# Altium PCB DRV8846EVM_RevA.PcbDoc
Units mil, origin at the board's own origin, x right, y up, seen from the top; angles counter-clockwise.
Board outline 2000 x 3000 mil, 2 copper layers (Top Layer, Bottom Layer), stack 62 mil thick; 51 components, 58 nets, 255 pads, 188 vias.
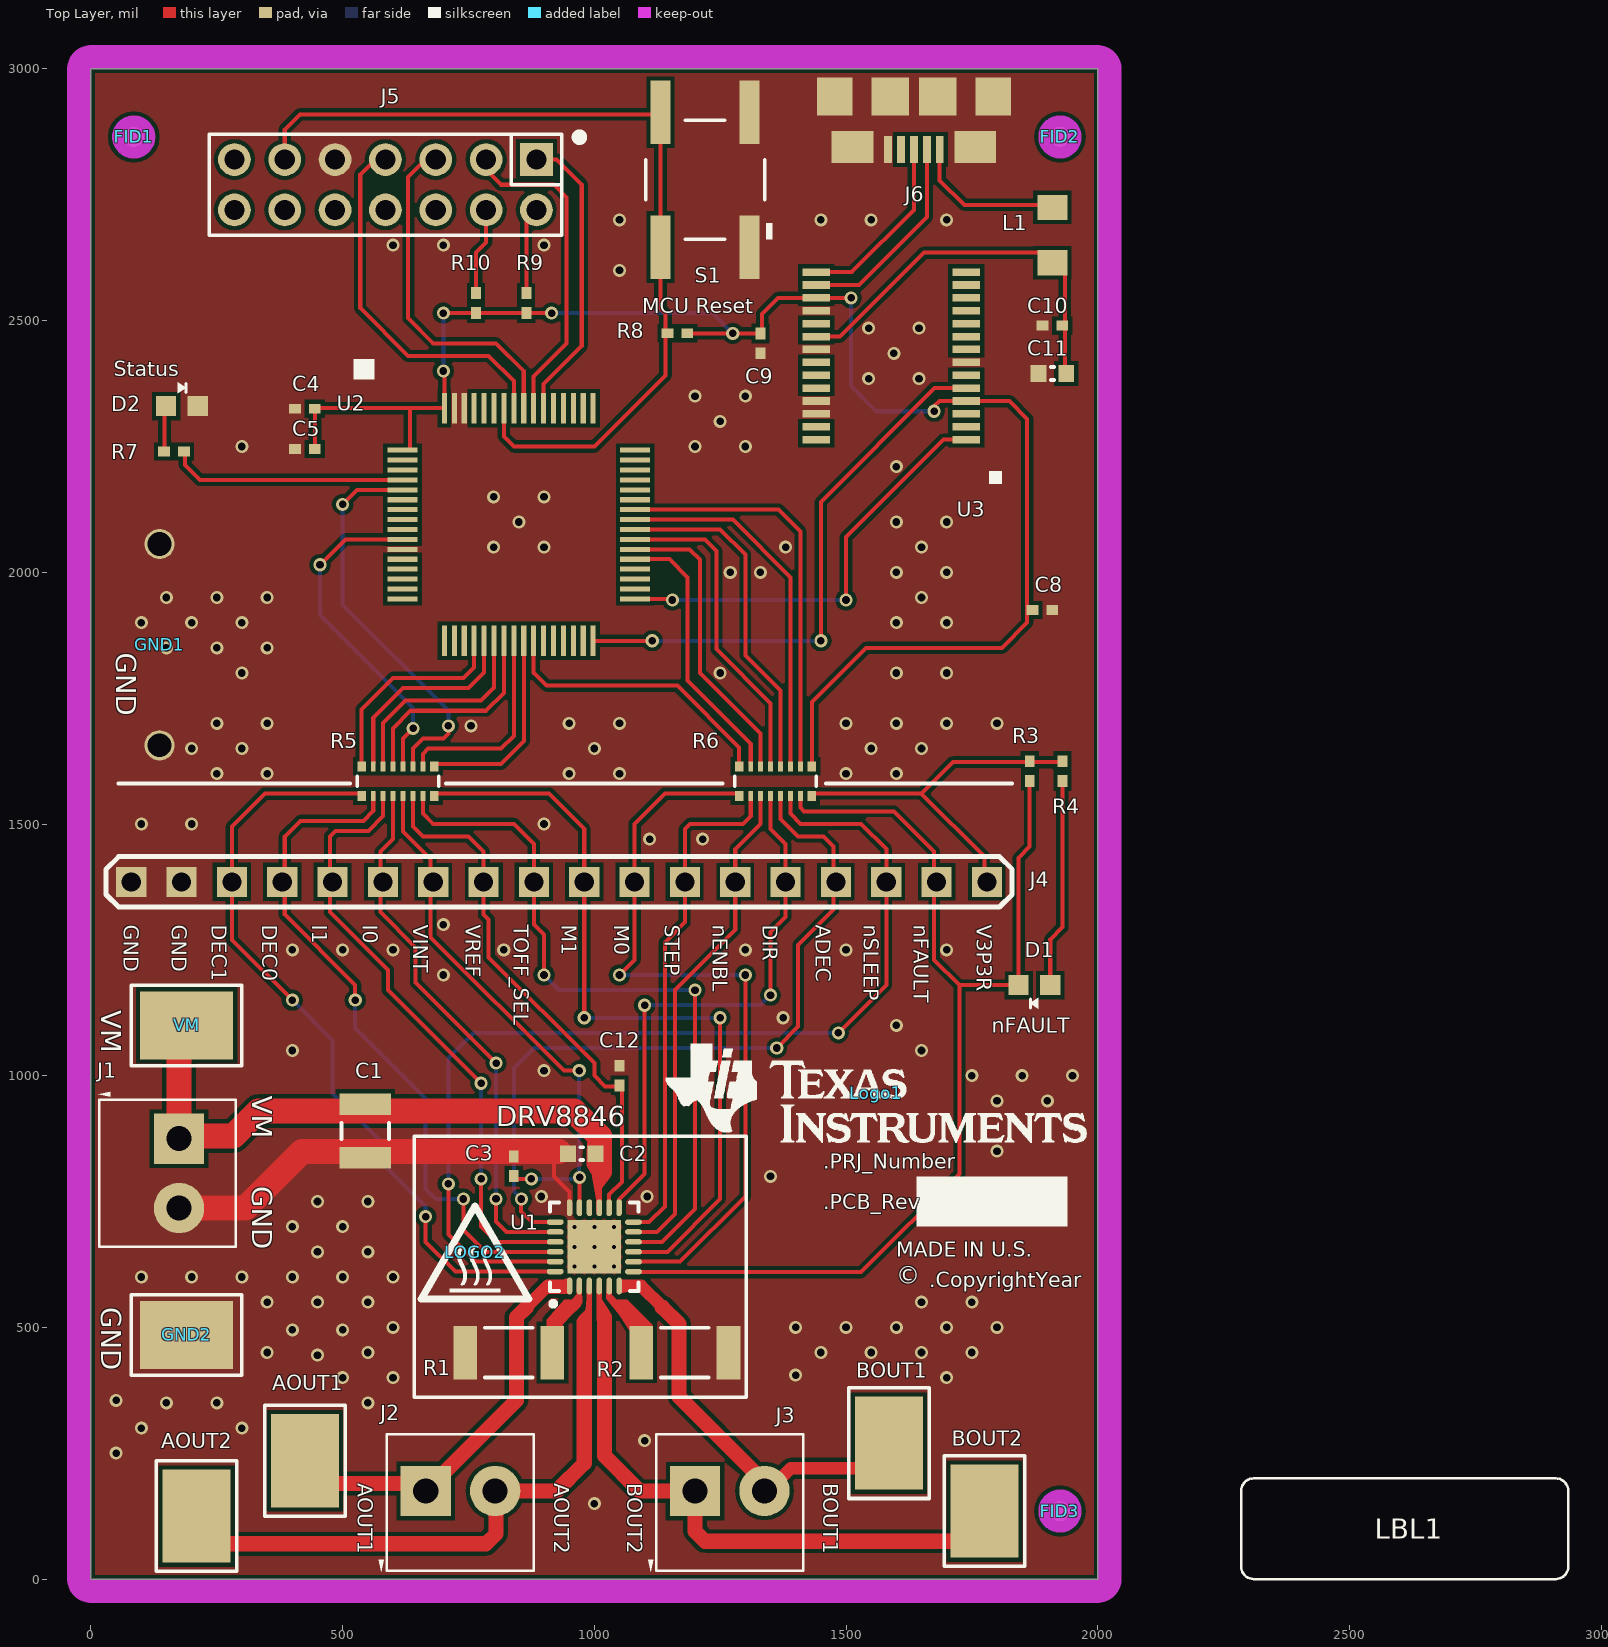
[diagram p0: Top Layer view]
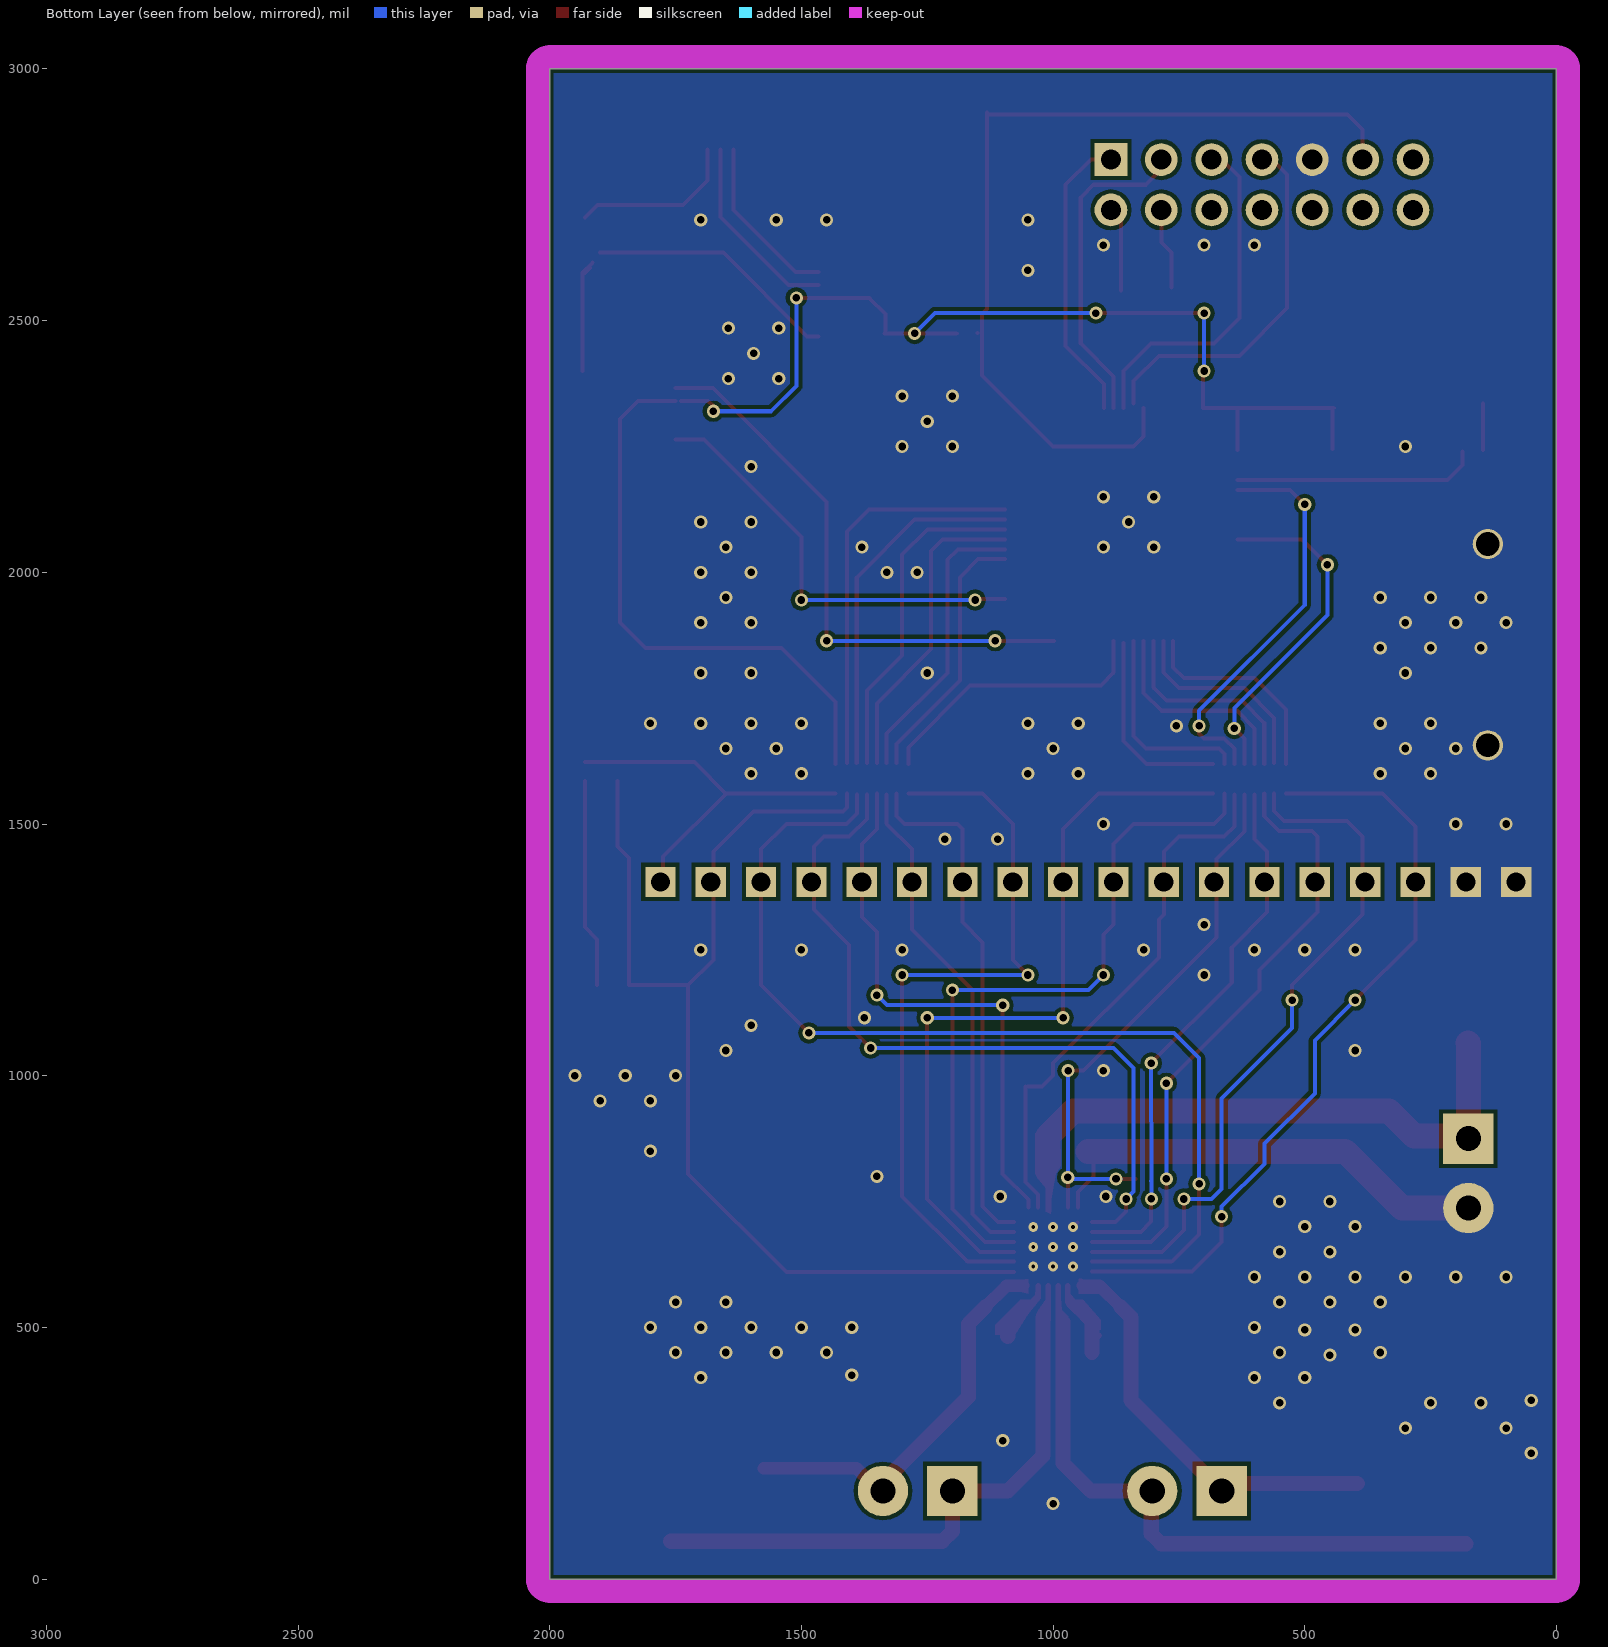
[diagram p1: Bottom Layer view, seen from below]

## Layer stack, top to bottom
Top Layer: signal copper 1.4
Dielectric: core 59.2, FR-4, Dk 4.8
Bottom Layer: signal copper 1.4

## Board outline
0,0 0,3000 2000,3000 2000,0

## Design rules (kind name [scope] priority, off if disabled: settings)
AcuteAngle [All] p1: minimum=4.50000000000000E+0001 checktracksonly=FALSE
AssemblyTestPointUsage [All] p1: valid=2
Clearance [All] p1: gap=7.8
Clearance Stitching_GND [IsStitchingVia and InNet('GND') vs (IsVia and (Not IsStitchingVia)) Or IsPad] p2: gap=10
Clearance Clearance_BoardEdge_MountingHoles [OnCopper and InComponentClass('Mounting Holes') vs IsKeepOut] p3: gap=40
Clearance Clearance_BoardEdge_Poly [OnCopper and InPoly vs IsKeepOut] p4: gap=25
Clearance Clearance_Poly_GND [InNamedPolygon('Bottom Layer-GND') or InNamedPolygon('Top Layer-GND')] p5: gap=10
Clearance Clearance_BoardEdge [OnCopper and Not InComponentClass('Logo') and not InComponentClass('FiducialMark') and not InRegion(1000,500,4000,800) and Not IsKeepout vs IsKeepOut] p6: gap=75
Clearance Clearance_Poly [InPolygon] p7: gap=25
ComponentClearance ComponentClearance_Logo [InComponentClass('Logo')] p1: gap=50 collisioncheckmode=3 verticalgap=10 showdistances=FALSE
ComponentClearance ComponentClearance_ScrewToNut [(HasFootprint('NY PMS 440 0025 PH')) vs (HasFootprint('Keystone_1902C'))] p2: gap=5 collisioncheckmode=3 verticalgap=10 showdistances=FALSE
ComponentClearance ComponentClearance_MountingHoles [InComponentClass('Mounting Holes')] p3: gap=250 collisioncheckmode=3 verticalgap=100000 showdistances=FALSE
ComponentClearance ComponentClearance_SmallPassives [HasFootprint('0201*') or HasFootprint('0402*') or HasFootprint('0508') or HasFootprint('0603*') or HasFootprint('0612') or HasFootprint('0805*') or HasFootprint('0815*') or HasFootprint('0830*') or HasFootprint('1206*') or HasFootprint('1210*') or HasFootprint('1808*') or HasFootprint('1812*') or HasFootprint('1825*') or HasFootprint('2010*') or HasFootprint('2220*') or HasFootprint('2225*') or HasFootprint('2512*') or HasFootprint('2728*') or HasFootprint('3518*') vs HasFootprint('0201*') or HasFootprint('0402*') or HasFootprint('0508') or HasFootprint('0603*') or HasFootprint('0612') or HasFootprint('0805*') or HasFootprint('0815*') or HasFootprint('0830*') or HasFootprint('1206*') or HasFootprint('1210*') or HasFootprint('1808*') or HasFootprint('1812*') or HasFootprint('1825*') or HasFootprint('2010*') or HasFootprint('2220*') or HasFootprint('2225*') or HasFootprint('2512*') or HasFootprint('2728*') or HasFootprint('3518*')] p4: gap=20 collisioncheckmode=3 verticalgap=10 showdistances=FALSE
ComponentClearance ComponentClearance_THtoSMT [IsThruComponent vs IsSMTComponent] p5: gap=100 collisioncheckmode=3 verticalgap=30 showdistances=FALSE
ComponentClearance ComponentClearance_THtoTH [IsThruComponent vs IsThruComponent] p6: gap=118.11 collisioncheckmode=3 verticalgap=30 showdistances=FALSE
ComponentClearance [All] p7: gap=40 collisioncheckmode=3 verticalgap=10 showdistances=FALSE
DiffPairsRouting [All] p1: maxlimit=100 minlimit=10 mostfreqgap=10 maxuncoupledlength=1000
FabricationTestPointUsage TestPointUsage [All] p1: valid=2 allowmultiple=FALSE
FabricationTestpoint Testpoint [All] p1: side=3 testpointundercomponent=TRUE minsize=40 maxsize=100 preferedsize=60 minholesize=0 maxholesize=40 preferedholesize=32 testpointgrid=1 allowsidetop=TRUE allowsidebottom=TRUE usegrid=TRUE gridtolerance=0.01
FanoutControl Fanout_LCC [IsLCC] p1: bgadir=Out bgaviamode=Centered fanoutstyle=Auto fanoutdirection=Alternating viagrid=1 // Fanout_LCC (Default Rule)
FanoutControl Fanout_BGA [IsBGA] p2: bgadir=Out bgaviamode=Centered fanoutstyle=Auto fanoutdirection=Alternating viagrid=1 // Fanout_BGA (Default Rule)
FanoutControl Fanout_Default [All] p4: bgadir=Out bgaviamode=Centered fanoutstyle=Auto fanoutdirection=Alternating viagrid=1 // Fanout_Default (Default Rule)
FanoutControl Fanout_Small [(CompPinCount < 5)] p5: bgadir=Out bgaviamode=Centered fanoutstyle=Auto fanoutdirection=OutThenIn viagrid=1 // Fanout_Small (Default Rule)
HoleSize [All] p1: absolutevalues=TRUE maxlimit=251 minlimit=7.8 maxpercent=80.000 minpercent=20.000
MinimumAnnularRing MinimumAnnularRing_ThermalPadVias [IsVia and InAnyComponent] p1: minimumring=5.91
MinimumAnnularRing [All] p2: minimumring=5
MinimumSolderMaskSliver MinimumSolderMaskSliver_Logo [InComponentClass('Logo') vs InComponentClass('Logo')] p1: minsoldermaskwidth=0.7
MinimumSolderMaskSliver [All] p2: minsoldermaskwidth=2
PlaneClearance [All] p1: clearance=15
PlaneConnect [All] p1: planeconnectstyle=Relief reliefexpansion=10 reliefentries=4 reliefconductorwidth=10 reliefairgap=10
PolygonConnect [All] p1: connectstyle=Direct reliefconductorwidth=10 reliefentries=4 polygonreliefangle="90 Angle" airgapwidth=10
PolygonConnect PolygonConnect_1 [IsNamedPolygon('Top Layer-GND') or IsNamedPolygon('Bottom Layer-GND') vs Not (InComponent('U1') or InComponent('U2') or InComponent('J1') or InComponent('J2') or IsStitchingVia or IsVia)] p2: connectstyle=Relief reliefconductorwidth=10 reliefentries=4 polygonreliefangle="90 Angle" airgapwidth=10
RoutingVias ThermalPadVias [IsVia and InAnyComponent] p1: holewidth=7.87 width=19.68 viastyle="Through Hole" minholewidth=7.87 minwidth=19.68 maxholewidth=12.99 maxwidth=23.62
RoutingVias [All] p2: holewidth=16 width=34 viastyle="Through Hole" minholewidth=7.87 minwidth=26 maxholewidth=40 maxwidth=65
SMDToCorner [All] p1: distance=30000
SilkToSilkClearance [All] p1: silktosilkclearance=5
SilkscreenOverComponentPads [All] p1: minsilkscreentomaskgap=5
SolderMaskExpansion [All] p1: expansion=1.97
Width [All] p1: maxlimit=100 minlimit=6 preferedwidth=10 checkconnectedcopper=TRUE
13 further rules are at their usual default settings.

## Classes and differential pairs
component class DRV8846EVM_RevA: AOUT1 AOUT2 BOUT1 BOUT2 C1 C2 C3 C12 D1 GND1 GND2 J1 J2 J3 J4 R1 R2 R3 R4 R5 R6 U1 VM
component class DRV8846EVM_MSP430F2617_RevA: C4 C5 C8 C9 C10 C11 D2 J5 J6 L1 R7 R8 R9 R10 S1 U2 U3
component class Label: LBL1
component class AssemblyNote: ZZ1 ZZ2 ZZ3 ZZ4 ZZ5
component class FiducialMark: FID1 FID2 FID3
component class Hardware_ANSI-B: FID1 FID2 FID3 LBL1 Logo1 LOGO2 ZZ1 ZZ2 ZZ3 ZZ4 ZZ5
component class Logo: Logo1

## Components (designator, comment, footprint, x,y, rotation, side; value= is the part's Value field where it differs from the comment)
AOUT1 "5016" Testpoint_Keystone_Compact 425,235 r90 top
AOUT2 "5016" Testpoint_Keystone_Compact 210,125 r90 top
BOUT1 "5016" Testpoint_Keystone_Compact 1585,270 r90 top
BOUT2 "5016" Testpoint_Keystone_Compact 1775,135 r90 top
C1 "GMK325AB7106MM-T" 1210L 545,890 r270 top
C2 "06035C104KAT2A" 0603L 975,845 r180 top
C3 "C1005X5R1E225K050BC" 0402L 840,820 r90 top
C4 "GRM155R61A104KA01D" 0402L 425,2325 r180 top
C5 "GRM155R61A104KA01D" 0402L 425,2245 r180 top
C8 "GRM155R61A105KE15D" 0402L 1890,1925 r0 top
C9 "GRM155R61A104KA01D" 0402L 1330,2455 r270 top
C10 "GRM155R61A104KA01D" 0402L 1910,2490 r180 top
C11 "CGB3B1X5R1A475K055AC" 0603L 1910,2395 r180 top
C12 "C1005X5R0J104K" 0402L 1050,1000 r90 top
D1 "D_LED_603_RED" LED603 1875,1180 r0 top
D2 "LTST-C190GKT" LED603 180,2330 r180 top
FID1 "Fiducial" Fiducial10-20 85,2865 r90 top
FID2 "Fiducial" Fiducial10-20 1925,2865 r90 top
FID3 "Fiducial" Fiducial10-20 1925,135 r90 top
GND1 "D3082-05" GND_BRIDGE 215,2135 r180 top
GND2 "5016" Testpoint_Keystone_Compact 190,485 r180 top
J1 "ED555/2DS" TERM_BLK_ED555-2DS 175,875 r270 top
J2 "ED555/2DS" TERM_BLK_ED555-2DS 665,175 r0 top
J3 "ED555/2DS" TERM_BLK_ED555-2DS 1200,175 r0 top
J4 "HEADER_1X18" HEADER_1X18 80,1385 r0 top
J5 "PEC07DAAN" CONN_PEC07DAAN 585,2770 r180 top
J6 "ZX62-B-5PA(11)" CONN_USB_micro_ZX62-B-5PA 1635,2840 r180 top
L1 "MI0805K400R-10" 0805-IND 1910,2670 r90 top
LBL1 "Size: 0.65\" x 0.20 \"" Label_650x200 2610,100 r0 top
Logo1 "Texas Instruments" TI_Stacked_Overlay_Small 1560,965 r0 top
LOGO2 "CAUTION HOT SURFACE" IEC_HotSurface_Small 763,649 r0 top
R1 "CSRN2010FKR250" 2010L 830,450 r0 top
R2 "CSRN2010FKR250" 2010L 1180,450 r180 top
R3 "CRCW04024K99FKED" 0402L 1865,1605 r90 top
R4 "CRCW0402510RJNED" 0402L 1930,1605 r90 top
R5 "EXB-2HV330JV" RESCAXS_EXB-2HV 610,1585 r0 top
R6 "EXB-2HV330JV" RESCAXS_EXB-2HV 1360,1585 r0 top
R7 "CRCW0402330RJNED" 0402L 165,2240 r0 top
R8 "CRCW04023K32FKED" 0402L 1165,2475 r0 top
R9 "ERJ-2GE0R00X" 0402L 865,2535 r90 top
R10 "ERJ-2GE0R00X" 0402L 765,2535 r90 top
S1 "EVQP1D05M" SW_EVQxxx05M 1220,2780 r180 top
U1 "DRV8846RGE" RGE0024H_MDBU 1000,660 r90 top
U2 "MSP430F2617TPMR" PM_S-PQFP-G64 850,2095 r270 top
U3 "FT232RL" SSOP28 1590,2430 r180 top
VM "5016" Testpoint_Keystone_Compact 190,1100 r180 top
ZZ1 "This Assembly Note is for PCB labels only" AssemblyNoteLabel 180,3950 r0 top
ZZ2 "These assemblies are ESD sensitive, ESD precautions shall be observed." AssemblyNote 180,3840 r0 top
ZZ3 "These assemblies must be clean and free from flux and all contaminants. Use of no clean flux is not acceptable." AssemblyNote 180,3740 r0 top
ZZ4 "These assemblies must comply with workmanship standards IPC-A-610 Class 2, unless otherwise specified." AssemblyNote 180,3640 r0 top
ZZ5 "Shorting plug GND1 shall be raised to minimum height of 250mils above PCB" AssemblyNote 180,3540 r0 top

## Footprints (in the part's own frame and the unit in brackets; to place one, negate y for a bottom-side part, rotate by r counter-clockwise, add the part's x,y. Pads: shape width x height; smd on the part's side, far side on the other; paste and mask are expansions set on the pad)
0402L [mm] "0402 from SM-752 data"
  rect 0.6x0.5 smd: 1(-0.5,0) 2(0.5,0)
  body extent -0.55,-0.3 0.55,0.3, height 0.6
0603L [mm] "0603 from SM-752 data"
  rect 0.8x0.85 smd: 1(-0.7,0) 2(0.7,0)
  silkscreen extent -0.07,-0.33 0.07,0.33, body extent -0.87,-0.47 0.87,0.47, height 0.85
0805-IND [mil]
  rect 50x60 smd mask+2: 1(-55,0) 2(55,0)
1210L [mm] "1210 from SM-752 data"
  rect 1.1x2.6 smd: 1(-1.35,0) 2(1.35,0)
  silkscreen extent -0.4,-1.2 0.4,1.2, body extent -1.7,-1.35 1.7,1.35, height 1.35
2010L [mm]
  rect 1.2x2.7 smd: 1(-2.2,0) 2(2.2,0)
  silkscreen extent -1.2,-1.25 1.2,1.25, body extent -2.73,-1.45 2.73,1.45, height 1.66
AssemblyNote [mil] "Assembly Note"
AssemblyNoteLabel [mil] "Assembly Note for PCB Labels"
CONN_PEC07DAAN [mm] "SULLINS"
  rect 1.65x1.65 hole 1.016 mask+0: 1(-7.62,-1.27)
  round 1.65 hole 1.016 mask+0: 2(-7.62,1.27) 3(-5.08,-1.27) 4(-5.08,1.27) 5(-2.54,-1.27) 6(-2.54,1.27) 7(0,-1.27) 8(0,1.27) 9(2.54,-1.27) 10(2.54,1.27) 11(5.08,-1.27) 12(5.08,1.27) 13(7.62,-1.27) 14(7.62,1.27)
  silkscreen extent -9.99,-2.6 8.89,2.54, body extent -8.95,-2.6 8.95,2.6, height 11.43
CONN_USB_micro_ZX62-B-5PA [mm] "Hirose"
  rect 0.4x1.35 smd: 1(-1.3,0) 2(-0.65,0) 3(0,0) 4(0.65,0) 5(1.3,0)
  rect 1.9x1.9 smd: 6(-1.2,-2.675) 7(1.2,-2.675)
  rect 1.8x1.9 smd: 8(-4,-2.675) 9(4,-2.675)
  rect 2.1x1.6 smd: 10(-3.1,-0.125) 11(3.1,-0.125)
  body extent -3.75,-5.33 3.75,0.18, height 2.55
Fiducial10-20 [mm]
  round 1 smd paste-0.5 mask+0.5: 1(0,0)
  Top Layer keep-out circle w1.178: c0,0 r0.5
GND_BRIDGE [mm] "400 Mil space ground connection for scope probes"
  round 1.524 hole 1.2: 1(2,12.16) 2(2,2)
HEADER_1X18 [mil]
  rect 60x60 hole 38: 1(0,0) 2(100,0) 3(200,0) 4(300,0) 5(400,0) 6(500,0) 7(600,0) 8(700,0) 9(800,0) 10(900,0) 11(1000,0) 12(1100,0) 13(1200,0) 14(1300,0) 15(1400,0) 16(1500,0) 17(1600,0) 18(1700,0)
  silkscreen extent -50,-50 1750,50
IEC_HotSurface_Small [mil]
  silkscreen extent -107,-93 107,92
Label_650x200 [mil] "Thermal Transfer Label"
  silkscreen extent -325,-100 325,100, body extent -326,-101 326,101, height 1
LED603 [mil]
  rect 40x40 smd: 1(-32.2,-0.1) 2(30.8,-0.1)
  silkscreen extent -10,-47 7,-25
PM_S-PQFP-G64 [mil]
  rect 10x60 smd mask+2: 1(-147.7,-231.1) 2(-128,-231.1) 3(-108.3,-231.1) 4(-88.6,-231.1) 5(-68.9,-231.1) 6(-49.2,-231.1) 7(-29.5,-231.1) 8(-9.8,-231.1) 9(9.9,-231.1) 10(29.6,-231.1) 11(49.3,-231.1) 12(69,-231.1) 13(88.7,-231.1) 14(108.4,-231.1) 15(128.1,-231.1) 16(147.8,-231.1) 33(147.8,230.9) 34(128.1,230.9) 35(108.4,230.9) 36(88.7,230.9) 37(69,230.9) 38(49.3,230.9) 39(29.6,230.9) 40(9.9,230.9) 41(-9.8,230.9) 42(-29.5,230.9) 43(-49.2,230.9) 44(-68.9,230.9) 45(-88.6,230.9) 46(-108.3,230.9) 47(-128,230.9) 48(-147.7,230.9)
  rect 60x10 smd mask+2: 17(231,-147.8) 18(231,-128.1) 19(231,-108.4) 20(231,-88.7) 21(231,-69) 22(231,-49.3) 23(231,-29.6) 24(231,-9.9) 25(231,9.8) 26(231,29.5) 27(231,49.2) 28(231,68.9) 29(231,88.6) 30(231,108.3) 31(231,128) 32(231,147.7) 49(-231,147.7) 50(-231,128) 51(-231,108.3) 52(-231,88.6) 53(-231,68.9) 54(-231,49.2) 55(-231,29.5) 56(-231,9.8) 57(-231,-9.9) 58(-231,-29.6) 59(-231,-49.3) 60(-231,-69) 61(-231,-88.7) 62(-231,-108.4) 63(-231,-128.1) 64(-231,-147.8)
  silkscreen extent -329,-328 -289,-288
RESCAXS_EXB-2HV [mm] "Panasonic Resistor Array"
  rect 0.425x0.5 smd mask+0.07: 1(-1.837,-0.75) 8(1.837,-0.75) 9(1.837,0.75) 16(-1.837,0.75)
  rect 0.25x0.5 smd mask+0.07: 2(-1.25,-0.75) 3(-0.75,-0.75) 4(-0.25,-0.75) 5(0.25,-0.75) 6(0.75,-0.75) 7(1.25,-0.75) 10(1.25,0.75) 11(0.75,0.75) 12(0.25,0.75) 13(-0.25,0.75) 14(-0.75,0.75) 15(-1.25,0.75)
  silkscreen extent -2.05,-0.25 2.05,0.25, body extent -1.95,-0.8 1.95,0.8, height 0.55
RGE0024H_MDBU [mm]
  oval 0.85x0.28 smd paste-0.025 mask+0.07: 1(-1.975,1.25) 2(-1.975,0.75) 3(-1.975,0.25) 4(-1.975,-0.25) 5(-1.975,-0.75) 6(-1.975,-1.25) 13(1.975,-1.25) 14(1.975,-0.75) 15(1.975,-0.25) 16(1.975,0.25) 17(1.975,0.75) 18(1.975,1.25)
  oval 0.28x0.85 smd paste-0.025 mask+0.07: 7(-1.25,-1.975) 8(-0.75,-1.975) 9(-0.25,-1.975) 10(0.25,-1.975) 11(0.75,-1.975) 12(1.25,-1.975) 19(1.25,1.975) 20(0.75,1.975) 21(0.25,1.975) 22(-0.25,1.975) 23(-0.75,1.975) 24(-1.25,1.975)
  rect 2.7x2.7 smd paste-1.35 mask+0.07: 25(0,0)
  silkscreen extent -3,-2.22 2.22,2.22, body extent -2.07,-2.07 2.07,2.07, height 1
SSOP28 [mil]
  rect 55x15 smd: 1(-148.9,166.4) 2(-148.9,140.8) 3(-148.9,115.2) 4(-148.9,89.6) 5(-148.9,64) 6(-148.9,38.4) 7(-148.9,12.8) 8(-148.9,-12.8) 9(-148.9,-38.4) 10(-148.9,-64) 11(-148.9,-89.6) 12(-148.9,-115.2) 13(-148.9,-140.8) 14(-148.9,-166.4) 15(149.1,-166.4) 16(149.1,-140.8) 17(149.1,-115.2) 18(149.1,-89.6) 19(149.1,-64) 20(149.1,-38.4) 21(149.1,-12.8) 22(149.1,12.8) 23(149.1,38.4) 24(149.1,64) 25(149.1,89.6) 26(149.1,115.2) 27(149.1,140.8) 28(149.1,166.4)
  silkscreen extent -220,229 -195,254
SW_EVQxxx05M [mm] "Panasonic EVQP0/EVQP1/EVQ9P 6mm Square Long Travel Light Touch Switch"
  rect 1x3.2 smd: 1(-2.25,3.4) 2(-2.25,-3.4) 3(2.25,-3.4) 4(2.25,3.4)
  silkscreen extent -3.4,-3 3,3, body extent -3,-3 3,3, height 5
TERM_BLK_ED555-2DS [mil]
  rect 100x100 hole 50: 1(0,0)
  round 100 hole 50: 2(138,0)
  silkscreen extent -93,-161 215,113, body extent -69,-150 207,106, height 323
Testpoint_Keystone_Compact [mil] "Compact SMT test point"
  rect 185x135 smd: 1(0,0)
  silkscreen extent -110,-80 110,80, body extent -75,-56 75,56, height 91
TI_Stacked_Overlay_Small [mil]
  silkscreen extent -418,-98 418,98

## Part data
AOUT1 AOUT2 BOUT1 BOUT2 GND2 VM: "Test Point, Compact, SMT"
C1: "CAP, CERM, 10uF, 35V, +/-20%, X7R, 1210"
C2: "CAP, CERM, 0.1uF, 50V, +/-10%, X7R, 0603"
C3: "CAP, CERM, 2.2uF, 25V, +/-10%, X5R, 0402"
C4 C5 C9 C10: "CAP, CERM, 0.1uF, 10V, +/-10%, X5R, 0402"
C8: "CAP, CERM, 1uF, 10V, +/-10%, X5R, 0402"
C11: "CAP, CERM, 4.7uF, 10V, +/-10%, X5R, 0603"
C12: "CAP, CERM, 0.1uF, 6.3V, +/-10%, X5R, 0402"
D1: "Diode, LED, Red, 2.1-V, 20-mA, 6-mcd"
D2: library part D_LED_603_GRN, "Diode, LED, Green, 2.1-V, 20-mA, 6-mcd"
FID1 FID2 FID3: "Fiducial mark.  There is nothing to buy or mount."
GND1: library part GND_Bridge
J1 J2 J3: "Terminal Block, 6A, 3.5mm Pitch, 2-Pos, TH"
J4: "Header, Male 18-pin, 100mil spacing,"
J5: "Header, 100mil, 7x2, Tin plated, TH"
J6: "Connector, micro USB Type B, Receptacle, R/A, SMD"
L1: library part BEAD-MI0805K_SERIES, "Bead, Ferrite, yymA"
LBL1: library part THT-14-423-10, "Thermal Transfer Printable Labels, 0.650\" W x 0.200\" H - 10,000 per roll"
Logo1: library part TI_Logo, "Texas Instrument Corporate Signature"
LOGO2: library part IEC_HotSurface, "IEC 61010-1 Hot Surface Warning"
R1 R2: "RES, 0.25 ohm, 1%, 1W, 2010"
R3: "RES, 4.99k ohm, 1%, 0.063W, 0402"
R4: "RES, 510 ohm, 5%, 0.063W, 0402"
R5 R6: "RES, 33 ohm, 5%, 0.0625W, Resistor Array - 8x1"
R7: "RES, 330 ohm, 5%, 0.063W, 0402"
R8: "RES, 3.32k ohm, 1%, 0.063W, 0402"
R9 R10: "RES, 0 ohm, 5%, 0.063W, 0402"
S1: "Switch, Tactile, SPST-NO, 0.05A, 12V, SMT"
U1: library part DRV8846_2_RGE
U2: library part MSP430F23XTPM, "IC, Mixed Signal Microcontroller, xKB+256B Flash Memory, 1KB RAM"
U3: "IC,  USB  UART"
ZZ1: library part AssemblyNoteLabel
ZZ2 ZZ3 ZZ4 ZZ5: library part AssemblyNote

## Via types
v1: diameter 26, hole 15, Top Layer to Bottom Layer, tented both sides, 178 vias
v2: diameter 19.68, hole 7.87, Top Layer to Bottom Layer, 9 vias
v3: diameter 26, hole 15, Top Layer to Bottom Layer, tented top, 1 vias

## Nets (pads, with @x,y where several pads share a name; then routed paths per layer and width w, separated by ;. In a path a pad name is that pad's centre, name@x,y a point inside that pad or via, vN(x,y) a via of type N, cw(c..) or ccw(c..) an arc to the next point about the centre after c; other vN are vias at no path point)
ADEC: J4.15 R6.5 U1.19 | length 1530.2
  Top Layer w8: v1@854.79,756 854.79,730.21 875.79,709.21 U1.19 ; v1(1362.5,1055) 1405,1097.5 1405,1260 1475,1330 1475,1455 1455,1475 1405,1475 1369.84,1510.16 R6.5@1369.84,1558.5
  Bottom Layer w8: v1(855,755) 840,770 840,1015 880,1055 v1(1362.5,1055)
AISEN: R1.2 U1.2 | length 211.1
  Top Layer w8: R1.2@916.61,445 R1.2@916.61,491.61
  Top Layer w11: R1.2@907.8,483.82 R1.2@916.61,475 ; 950,540 970.47,560.47 U1.2
  Top Layer w30: R1.2@922.8,450 922.8,512.8 950,540
AOUT1: AOUT1.1 J2.1 U1.1 | length 805.1
  Top Layer w25: 865,540 907.24,582.24 941,582.24
  Top Layer w30: AOUT1.1@395,190 680,190 845,355 845,520 865,540
AOUT2: AOUT2.1 J2.2 U1.3 | length 1254.5
  Top Layer w11: 980,511 990.16,521.16 U1.3
  Top Layer w30: AOUT2.1@180,70 785,70 805,90 J2.2@805,155 ; J2.2 925,175 980,230 980,511
BISEN: R2.2 U1.5 | length 125.7
  Top Layer w11: U1.5 1029.53,560.47 1090,500 R2.2@1090,491
  Top Layer w30: R2.2@1090,481.61 R2.2@1090,491
BOUT1: BOUT1.1 J3.2 U1.6 | length 773.8
  Top Layer w25: 1059,582.24 1092.76,582.24 1135,540 ; J3.2@1337.5,192.5 1362.5,192.5 1390,220 BOUT1.1@1575,220
  Top Layer w30: 1135,540 1168,507 1168,362 J3.2@1337.5,192.5
BOUT2: BOUT2.1 J3.1 U1.4 | length 1200.2
  Top Layer w8: 1009.84,537.16 1026,521
  Top Layer w11: 1009.84,537.16 U1.4
  Top Layer w30: 1020,520 1020,245 1090,175 J3.1 1200,95 1220,75 BOUT2.1@1760,75
DEC0: J4.4 R5.2 U1.22 | length 1392.4
  Top Layer w8: v1(525,1150) 525,1180 385,1320 385,1475 416,1506 541,1506 560.79,1525.79 R5.2@560.79,1560.47 ; v1(740,755) 740,693.67 783.52,650.16 U1.22
  Bottom Layer w8: v1(525,1150) 525,1095 665,955 665,775 685,755 v1(740,755)
DEC1: J4.3 R5.1 U1.24 | length 1551
  Top Layer w8: v1(400,1150) 280,1270 280,1495 345.47,1560.47 R5.1@537.66,1560.47 ; v1(665,720) 665,670 724.21,610.79 U1.24
  Bottom Layer w8: v1(400,1150) 480,1070 480,965 580,865 580,825 665,740 v1(665,720)
DIR: J4.14 R6.4 U1.13 | length 1106.8
  Top Layer w8: U1.13 1049.21,754.21 1100,805 v1(1100,1140) ; v1(1350,1160) 1350,1285.01 1380,1315.01 J4.14 1380,1460 1350.16,1489.84 R6.4@1350.16,1560.47
  Bottom Layer w8: v1(1100,1140) 1330,1140 v1(1350,1160)
DM: J6.2 U3.16 | length 384.9
  Top Layer w8: U3.16@1465.9,2570.8 1525.8,2570.8 1660.59,2705.59 J6.2
DP: J6.3 U3.15 | length 340.3
  Top Layer w8: U3.15@1465.9,2596.4 1511.4,2596.4 1635,2720 J6.3
GND: C1.2 C2.2 C3.2 C4.2 C5.2 C8.2 C9.2 C10.2 C11.2 C12.2 D2.1 GND1.1 GND1.2 GND2.1 J1.2 J4.1 J4.2 J5.9 J6.5 J6.6 J6.7 J6.8 J6.9 J6.10 J6.11 R1.1 R2.1 S1.1 S1.2 U1.18 U1.25 U2.11 U2.62 U2.63 U3.7 U3.18 U3.21 U3.25 U3.26 | length 939.3
  Top Layer w8: v1@795.7,2045.7 v1(800,2050) ; 930,840 920,830 920,800 950.79,769.21 U1.18 ; U1.25@951.78,708.22 v2(960.63,699.37)
  Top Layer w50: J1.2 307,737 419.43,849.43 930,849.43
  other v1: 1000,150 50,250 1100,275 100,300 300,300 150,350 250,350 550,350 50,355 500,400 600,400 1700,400 1400,405 450,445 350,450 550,450 1450,450 1550,450 1650,450 1750,450 400,495 500,495 600,500 1400,500 1500,500 1600,500 1700,500 1800,500 350,550 450,550 550,550 1650,550 1750,550 100,600 200,600 300,600 400,600 500,600 600,600 450,650 550,650 400,700 500,700 450,750 550,750 895,760 1105,760 1350,800 1800,850 1800,950 1900,950 1750,1000 1850,1000 1950,1000 900,1010 400,1050 1650,1050 1600,1100 1375,1115 700,1200 400,1250 500,1250 600,1250 820,1250 1300,1250 1500,1250 1700,1250 700,1300 1110,1470 1215,1470 100,1500 200,1500 900,1500 250,1600 350,1600 950,1600 1050,1600 1500,1600 1600,1600 200,1650 300,1650 1000,1650 1550,1650 1650,1650 755,1695 250,1700 350,1700 950,1700 1050,1700 1500,1700 1600,1700 1700,1700 1800,1700 300,1800 1250,1800 1600,1800 1700,1800 150,1850 250,1850 350,1850 100,1900 200,1900 300,1900 1600,1900 1700,1900 150,1950 250,1950 350,1950 1650,1950 1270,2000 1330,2000 1600,2000 1700,2000 900,2050 1380,2050 1650,2050 850,2100 1600,2100 1700,2100 800,2150 900,2150 1600,2210 300,2250 1200,2250 1300,2250 1250,2300 1200,2350 1300,2350 1545,2385 1645,2385 1595,2435 1545,2485 1645,2485 1050,2600 600,2650 700,2650 900,2650 1050,2700 1450,2700 1550,2700 1700,2700
  other v2: 960.63,620.63 1000,620.63 1039.37,620.63 960.63,660 1000,660 1039.37,660 1000,699.37 1039.37,699.37
I0: J4.6 R5.4 U1.20 | length 1070.1
  Top Layer w8: R5.4@600,1558.5 600,1470 575,1445 575,1325 645,1255 645,1185 v1(805,1025) ; v1@805,745 805,710 825.47,689.53 U1.20
  Bottom Layer w8: 804.7,790.78 v1(805,1025) ; v1@805,755 v1(804.7,755.3) 804.7,790.48 805,790.78
I1: J4.5 R5.3 U1.21 | length 1226.1
  Top Layer w8: R5.3@580.47,1560.47 580.47,1515.47 551,1486 486,1486 475,1475 475,1325 590,1210 590,1170 v1(775,985) ; v1(775,795) 775,700.17 805.33,669.84 U1.21
  Bottom Layer w8: v1(775,795) v1(775,985)
M0: J4.11 R6.1 U1.8 | length 1511
  Top Layer w8: v1(1050,1200) 1080,1230 1080,1500 1140.47,1560.47 R6.1@1287.66,1560.47 ; U1.8 1170.47,630.47 1300,760 v1(1300,1200)
  Bottom Layer w8: v1(1050,1200) v1(1300,1200)
M1: J4.10 R5.8 U1.9 | length 1547.5
  Top Layer w8: R5.8@682.34,1560.47 909.53,1560.47 980,1490 v3(980,1115) ; U1.9 1145.16,650.16 1250,755 v1(1250,1115)
  Bottom Layer w8: v3(980,1115) v1(1250,1115)
MSP_ADEC: R6.12 U2.40 | length 667.3
  Top Layer w8: U2.40@1095.9,2085.1 1249.9,2085.1 1300,2035 1300,1835 1369.84,1765.16 R6.12@1369.84,1621.48
MSP_BVREF: U2.6
MSP_CA7: U2.27
MSP_DEC0: R5.15 U2.21 | length 409.9
  Top Layer w8: R5.15@560.79,1621.48 560.79,1710.79 620,1770 750,1770 781,1801 U2.21
MSP_DEC1: R5.16 U2.20 | length 419.1
  Top Layer w8: R5.16@537.66,1619.53 537.66,1727.66 600,1790 740,1790 761.3,1811.3 U2.20
MSP_DIR: R6.13 U2.39 | length 621.7
  Top Layer w8: U2.39@1095.9,2065.4 1219.6,2065.4 1242.8,2042.2 1242.8,1847.2 1350.16,1739.84 R6.13@1350.16,1621.48
MSP_I0: R5.13 U2.23 | length 423.6
  Top Layer w8: R5.13@600.16,1619.53 600.16,1690.16 635,1725 785,1725 820.4,1760.4 U2.23
MSP_I1: R5.14 U2.22 | length 423.6
  Top Layer w8: R5.14@580.47,1619.53 580.47,1700.47 625,1745 775,1745 800.7,1770.7 U2.22
MSP_M0: R6.16 U2.26 | length 565.8
  Top Layer w8: U2.26 879.5,1800.5 905,1775 1165,1775 1287.66,1652.34 R6.16@1287.66,1619.53
MSP_M1: R5.9 U2.25 | length 391.5
  Top Layer w8: R5.9@682.34,1619.53 814.53,1619.53 860,1665 U2.25@860,1860
MSP_NENBL: R6.14 U2.38 | length 576.1
  Top Layer w8: U2.38@1095.9,2045.7 1189.3,2045.7 1210,2025 1210,1800 1330.47,1679.53 R6.14@1330.47,1621.48
MSP_NFAULT: R6.10 U2.42 | length 790.7
  Top Layer w8: U2.42@1095.9,2124.5 1365.5,2124.5 1409.21,2080.79 R6.10@1409.21,1621.48
MSP_NSLEEP: R6.11 U2.41 | length 710.2
  Top Layer w8: U2.41@1095.9,2104.8 1275.2,2104.8 1390,1990 R6.11@1390,1621.5
MSP_STEP: R6.15 U2.37 | length 524.6
  Top Layer w8: U2.37@1095.9,2026 1149,2026 1185,1990 1185,1784.99 1310.79,1659.2 R6.15@1310.79,1621.5
MSP_TOFF_SEL: R5.10 U2.24 | length 404.3
  Top Layer w8: R5.10@659.21,1619.53 659.21,1639.21 670,1650 815,1650 840.1,1675.1 U2.24
MSP_VINT: R5.12 U2.10 | length 680.2
  Top Layer w8: v1(455,2015) 505.4,2065.4 U2.10@633.9,2065.4 ; R5.12@619.84,1619.53 619.84,1669.84 v1(640,1690)
  Bottom Layer w8: v1(455,2015) 455,1915 640,1730 v1(640,1690)
MSP_VREF: R5.11 U2.5 | length 801
  Top Layer w8: v1(500,2135) 528.9,2163.9 U2.5@633.9,2163.9 ; R5.11@639.53,1619.53 639.53,1649.53 660,1670 700,1670 710,1680 v1(710,1695)
  Bottom Layer w8: v1(500,2135) 500,1935 710,1725 v1(710,1695)
NENBL: J4.13 R6.3 U1.11 | length 1001.1
  Top Layer w8: U1.11 1124.53,689.53 1160,725 1160,1170 1280,1290 1280,1450 1330.47,1500.47 R6.3@1330.47,1558.52
NetC10_1: C10.1 C11.1 L1.1 U3.20 | length 740.4
  Top Layer w8: U3.20@1465.9,2468.4 1488.4,2468.4 1655,2635 L1.1@1900,2635 ; L1.1@1915,2615 1934.68,2595.31 C11.1@1934.68,2400 ; L1.1@1920,2605 L1.1@1930,2595
NetD1_2: D1.2 R4.1 | length 415.4
  Top Layer w8: D1.2 1905.8,1270.8 1930,1295 R4.1
NetD2_2: D2.2 R7.1 | length 92.4
  Top Layer w8: R7.1@146.1,2242.6 D2.2@146.1,2335
NetJ5_1: J5.1 U2.54 | length 606.1
  Top Layer w8: J5.1@865,2820 925,2820 975,2770 975,2450 899.2,2374.2 U2.54
NetJ5_2: J5.2 R9.2 | length 168.3
  Top Layer w8: R9.2@865,2560 865,2700 J5.2
NetJ5_3: J5.3 U2.55 | length 657.2
  Top Layer w8: J5.3@765,2820 815,2770 920,2770 945,2745 945,2455 879.5,2389.5 U2.55
NetJ5_4: J5.4 R10.2 | length 162.8
  Top Layer w8: R10.2@765,2565.5 765,2635 785,2655 J5.4
NetJ5_5: J5.5 U2.56 | length 676.9
  Top Layer w8: J5.5@665,2820 630,2785 630,2505 680,2455 805,2455 859.8,2400.2 U2.56
NetJ5_7: J5.7 U2.57 | length 722.5
  Top Layer w8: J5.7@565,2815 565,2820 535,2790 535,2525 630,2430 790,2430 840,2380 U2.57@840,2335
NFAULT: D1.1 J4.17 R3.1 R6.7 U1.7 | length 2251
  Top Layer w8: U1.7@1077.76,610 1530,610 1725.1,805.1 1725.1,1179.9 ; R6.7@1409.21,1560.47 1409.21,1532.79 1417,1525 1595,1525 1675,1445 1675,1230 1725.1,1179.9 ; R3.1 1865,1455 1842.8,1432.8 D1.1 1725.1,1179.9
NSLEEP: J4.16 R6.6 U1.23 | length 2042.8
  Top Layer w8: v1(710,785) 710,684.67 764.2,630.47 U1.23 ; R6.6@1389.53,1558.52 1389.53,1520.47 1410,1500 1530,1500 1580,1450 1580,1180 v1(1485,1085)
  Bottom Layer w8: v1(710,785) 710,1035 760,1085 v1(1485,1085)
RST: J5.11 R8.1 S1.3 S1.4 U2.58 | length 1788.6
  Top Layer w8: J5.11 385,2880 415,2910 S1.3@1130,2910 ; U2.58 820.4,2269.6 840,2250 1000,2250 1141.38,2391.38 1141.38,2475 1141.38,2513.62 1131.42,2523.58 S1.4 S1.3 ; R8.1@1150,2475 R8.1@1150.5,2475
RX: U2.32 U3.5 | length 1120.9
  Top Layer w8: U2.32 v1(1115,1864) ; v1(1450,1864) 1450,2140 1676,2366 U3.5@1750,2366
  Bottom Layer w8: v1(1115,1864) v1@1449,1864
STATUS: R7.2 U2.4 | length 486.2
  Top Layer w8: R7.2@186.65,2240 186.65,2213.35 216.4,2183.6 U2.4@633.9,2183.6
STEP: J4.12 R6.2 U1.12 | length 1027.6
  Top Layer w8: U1.12 1109.04,709.21 1140,740.17 1140,1265 1180,1305 1180,1490 1190,1500 1295,1500 1310.79,1515.79 R6.2@1310.79,1560.47
TOFF_SEL: J4.9 R5.7 U1.10 | length 1440.6
  Top Layer w8: R5.7@659.21,1560.47 659.21,1520.79 680,1500 840,1500 880,1460 880,1300 900,1280 v1(900,1200) ; U1.10 1134.84,669.84 1200,735 v1@1200,1160
  Bottom Layer w8: v1(900,1200) 930,1170 v1(1200,1170)
TX: U2.33 U3.1 | length 857.1
  Top Layer w8: U2.33@1095.9,1947.2 v1@1152.8,1947.2 ; v1(1500,1945) 1500,2070 1693.6,2263.6 U3.1@1750,2263.6
  Bottom Layer w8: v1(1155,1945) v1(1500,1945)
V3P3: C4.1 C5.1 C8.1 C9.1 R6.9 R8.2 R9.1 R10.1 U2.1 U2.64 U3.4 U3.17 | length 3147.4
  Top Layer w8: C4.1@442.4,2326 633.9,2326 ; C5.1@445,2245 C4.1@445,2325 ; 625,2326 633.9,2326 ; U2.1@633.9,2242.7 633.9,2326 ; v1(700,2400) 702.2,2397.8 U2.64 633.9,2326 ; v1(700,2515) v1(915,2515) ; R8.2@1191.34,2474.68 C9.1@1335,2474.68 ; C9.1@1333.32,2478.32 1333.32,2513.32 1365.2,2545.2 v1(1510,2545.2) ; R6.9@1432.34,1619.53 1432.34,1742.34 1540,1850 1810,1850 1860,1900 1860,2305 1825,2340 U3.4@1750,2340 ; v1@1675,2330 1685.4,2340.4 U3.4
  Bottom Layer w8: v1(700,2400) v1(700,2515) ; v1(915,2515) 1234.68,2515 v1(1275,2474.68) ; v1@1510,2536 1510,2370 1560,2320 v1(1675,2320)
V3P3_R: J4.18 R3.2 R4.2 R6.8 | length 725.2
  Top Layer w8: R6.8@1432.34,1560.47 1650.47,1560.47 1712.72,1622.72 R4.2@1930,1622.72 ; 1650,1560 1775,1435 J4.18@1775,1410
VBUS: J6.1 L1.2 | length 335.6
  Top Layer w8: J6.1 1686.18,2778.82 1735,2730 1905,2730 L1.2@1930,2705
VINT: C3.1 J4.7 R5.5 U1.17 | length 1120.5
  Top Layer w8: R5.5@619.84,1558.5 619.84,1485.16 675,1430 675,1275 940,1010 v1(970,1010) ; C3.1@836,795 v1@866,795 ; U1.17 v1@970.47,795
  Bottom Layer w8: v1@866,795 v1@970,795 ; v1(970,1010) v1@970,795 ; v1(970.89,797.81) 970.89,795.89 v1@970,795
  other v1: 875,795
VM: C1.1 C2.1 J1.1 U1.15 VM.1 | length 1232.9
  Top Layer w8: C2.1@1000,840 C2.1@1009.84,830.16
  Top Layer w11: U1.15 C2.1@1009.84,830.16
  Top Layer w30: C2.1@1009.84,830.16 1009.84,880.16
  Top Layer w50: J1.1@165,880 J1.1@175,880 ; J1.1 J1.1@175,880 ; VM.1@176,1065 175,1064 J1.1@175,880 ; 1009.84,880.16 960,930 333,930 283,880 J1.1@175,880
VREF: C12.1 J4.8 R5.6 U1.14 | length 1070.7
  Top Layer w8: R5.6@639.53,1558.52 639.53,1495.47 660,1475 750,1475 780,1445 780,1320 790,1310 790,1235 1000,1025 1000,1000 1021.63,978.37 C12.1@1050,978.37 ; U1.14 1029.53,763.53 1055,789 C12.1@1055,978.35
pads on no net: FID1.1 FID2.1 FID3.1 J5.6 J5.8 J5.10 J5.12 J5.13 J5.14 J6.4 U1.16 U2.2 U2.3 U2.7 U2.8 U2.9 U2.12 U2.13 U2.14 U2.15 U2.16 U2.17 U2.18 U2.19 U2.28 U2.29 U2.30 U2.31 U2.34 U2.35 U2.36 U2.43 U2.44 U2.45 U2.46 U2.47 U2.48 U2.49 U2.50 U2.51 U2.52 U2.53 U2.59 U2.60 U2.61 U3.2 U3.3 U3.6 U3.8 U3.9 U3.10 U3.11 U3.12 U3.13 U3.14 U3.19 U3.22 U3.23 U3.24 U3.27 U3.28

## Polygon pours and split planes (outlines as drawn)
GND on Top Layer "Top Layer-GND" (solid, remove dead copper, pour order 12): 0,-1 0,2999 2000,2999 2000,-1
GND on Bottom Layer "Bottom Layer-GND" (solid, remove dead copper, pour order 8): 0,0 0,3000 2000,3000 2000,0

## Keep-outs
Keep-Out Layer:
  lines w47.24: -23.62,0 ccw(c0,0) 0,-23.62 ; -23.62,0 ccw(c0,0) 0,-23.62 ; -23.62,0 -23.62,3000 ; -23.62,3000 cw(c0,3000) 0,3023.62 ; -23.62,3000 cw(c0,3000) 0,3023.62 ; 0,-23.62 2000,-23.62 ; 0,3023.62 2000,3023.62 ; 2000,-23.62 ccw(c2000,0) 2023.62,0 ; 2000,-23.62 ccw(c2000,0) 2023.62,0 ; 2000,3023.62 cw(c2000,3000) 2023.62,3000 ; 2000,3023.62 cw(c2000,3000) 2023.62,3000 ; 2023.62,0 2023.62,3000
  text ".Layer_Name" at 577,-858.49 h60

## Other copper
Top Layer:
  region net VM: 1035,886 986,886 985,825 985,821 993,807 995,805 1004,755 1004,731 1005,725 1015,730 1015,776 1032,798 1035,805
  region net BOUT1: 1062,570 1049,567 1049,597 1062,595
  region net BOUT2: 1015,556 1031,531 1031,530 1018,517 1024,511 1016,504 1014,504 1011,503 1005,513 1005,546
  region net AISEN: 940,555 955,555 966,567 970.47,570 976,561.57 976,549 972,541 967,536 946.4,516.61 916.61,491.61 905,495 905,515
  region net AOUT1: 949,567 895,567 894,568 942,597 949,597
  region net BISEN: 1045,555 1065,555 1115,505 1115,485 1075,485 1050,525 1025,556 1024,557 1024,571 1035,570 1035,565
  region net AOUT2: 985,558 995,558 995,505 986,501 969,521 983,535
  text ".Layer_Name" at 577,-858.49 h60
Bottom Layer:
  text ".Layer_Name" at 577,-858.49 h60

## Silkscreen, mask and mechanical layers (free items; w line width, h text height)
Top Overlay:
  rectangle: 1640,700 1940,800
  lines w7: 642,360.71 1302,360.71 1302,880 1075,880 642,880 642,360.71
  lines w8: 55,1580 515,1580 ; 705,1580 1255,1580 ; 1460,1580 1830,1580
  text "MCU Reset" at 1095,2515 h30
  text "Status" at 45,2390 h30
  text "GND" at 50,1840 h40 r270
  text "GND" at 65,1300 h30 r270
  text "GND" at 160,1300 h30 r270
  text "DEC1" at 240,1300 h30 r270
  text "DEC0" at 340,1300 h30 r270
  text "I1" at 440,1300 h30 r270
  text "I0" at 540,1300 h30 r270
  text "VINT" at 640,1300 h30 r270
  text "VREF" at 745,1300 h30 r270
  text "TOFF_SEL" at 840,1300 h30 r270
  text "M1" at 935,1300 h30 r270
  text "M0" at 1040,1300 h30 r270
  text "STEP" at 1140,1300 h30 r270
  text "nENBL" at 1235,1300 h30 r270
  text "DIR" at 1335,1300 h30 r270
  text "ADEC" at 1440,1300 h30 r270
  text "nSLEEP" at 1535,1300 h30 r270
  text "nFAULT" at 1635,1300 h30 r270
  text "V3P3R" at 1760,1300 h30 r270
  text "VM" at 20,1130 h40 r270
  text "nFAULT" at 1790,1085 h30
  text "VM" at 320,960 h40 r270
  text "DRV8846" at 804.84,900 h40
  text ".PRJ_Number" at 1455,815 h30
  text "GND" at 320,780 h40 r270
  text ".PCB_Rev" at 1455,735 h30
  text "MADE IN U.S." at 1600,640 h30
  text ".CopyrightYear" at 1665,580 h30
  text "©" at 1600,575 h60
  text "GND" at 20,540 h40 r270
  text "AOUT1" at 530,190 h30 r270
  text "AOUT2" at 920,190 h30 r270
  text "BOUT2" at 1065,190 h30 r270
  text "BOUT1" at 1455,190 h30 r270
  text ".Layer_Name" at 577,-858.49 h60
Bottom Overlay:
  text ".Layer_Name" at 577,-858.49 h60
Top Paste:
  text ".Layer_Name" at 577,-858.49 h60
Bottom Paste:
  text ".Layer_Name" at 577,-858.49 h60
Top Solder:
  text ".Layer_Name" at 577,-858.49 h60
  text ".Layer_Name" at 577,-858.49 h60
Bottom Solder:
  text ".Layer_Name" at 577,-858.49 h60
Drill Guide:
  text ".Layer_Name" at 577,-858.49 h60
M1 Board Outline:
  the board outline again, w8
  text ".Layer_Name" at 577,-858.49 h60
M2 Board Dimensions:
  rectangle: 124.5,-410.5 499.5,-285.5
  rectangle: -0.5,-285.5 124.5,-160.5
  lines w7: -0.5,-285.5 999.5,-285.5 ; 124.5,-410.5 124.5,-160.5 ; 249.5,-410.5 249.5,-160.5 ; 499.5,-410.5 499.5,-160.5 ; 749.5,-410.5 749.5,-160.5 ; -0.5,-410.5 -0.5,-160.5 999.5,-160.5 999.5,-410.5 -0.5,-410.5
  lines w10: -0.5,-475.5 -0.5,-455.5 ; 59.5,-485.5 -0.5,-465.5 ; 59.5,-445.5 -0.5,-465.5 ; 223.58,-465.5 -0.5,-465.5 ; 775.42,-465.5 999.5,-465.5 ; 939.5,-485.5 999.5,-465.5 ; 939.5,-445.5 999.5,-465.5 ; 999.5,-475.5 999.5,-455.5
  text "1000 (mil)" at 233.58,-501.49 h60
  text ".Layer_Name" at 577,-858.49 h60
M3 3D STEP Top:
  text ".Layer_Name" at 577,-858.49 h60
M4 3D STEP Bottom:
  text ".Layer_Name" at 577,-858.49 h60
M5 Assembly Top:
  lines w8: -292,-930.17 6308,-930.17 ; -292,-726.83 6310,-726.83 ; -292,-523.5 -292,-1133.5 3713,-1133.5 6310,-1133.5 6310,-523.5 -291.5,-523.5 -291.5,-1133.5 1284,-1133.5 ; 2173,-1133.5 2173,-523.5 ; 3440,-726.83 3440,-523.5 ; 4280,-726.83 4280,-523.5 ; 4902,-1140 4902,-937.17
  text "COMPONENTS MARKED 'DNP' SHOULD NOT BE POPULATED." at 1153.5,-318.5 h60
  text "ASSEMBLY VARIANT:" at 1153,-434 h60
  text ".VariantName" at 2189,-434 h60
  text "PCB VIEWED FROM TOP SIDE" at -228.5,-655.67 h60
  text "BOARD #:" at 2248,-655.67 h60
  text ".PRJ_Number" at 2793.5,-655.67 h60
  text "REV:" at 3638,-655.67 h60
  text ".PCB_Rev" at 3929.5,-655.67 h60
  text "SVN REV:" at 4476,-655.67 h60
  text ".VersionControl_RevNumber" at 4982,-655.67 h60
  text "IGNORE ->" at -228.5,-858.49 h60
  text "PLOT NAME =" at -228.5,-1064.34 h60
  text ".plot_File_Name" at 577,-1064.34 h60
  text "GENERATED    :" at 2250,-1064.34 h60
  text ".Print_Date" at 3119.5,-1064.34 h60
  text ".Print_Time" at 3848.5,-1064.34 h60
  text "TEXAS INSTRUMENTS" at 5113,-1064.34 h60
M6 Assembly Bottom:
  lines w8: -292.5,-727.33 6309.5,-727.33 ; -290.5,-930.67 6309.5,-930.67 ; 1115.5,-1140.5 1115.5,-937.67 ; 1737.5,-727.33 1737.5,-524 ; 2577.5,-727.33 2577.5,-524 ; 3844.5,-1134 3844.5,-524 ; 4733.5,-1134 6309,-1134 6309,-524 -292.5,-524 -292.5,-1134 2304.5,-1134 6309.5,-1134 6309.5,-524
  text "COMPONENTS MARKED 'DNP' SHOULD NOT BE POPULATED." at 6102,-318 h60
  text ".VariantName" at 5058,-434 h60
  text "ASSEMBLY VARIANT:" at 6097,-434 h60
  text ".VersionControl_RevNumber" at 1035.5,-656.17 h60
  text "SVN REV:" at 1541.5,-656.17 h60
  text ".PCB_Rev" at 2088,-656.17 h60
  text "REV:" at 2379.5,-656.17 h60
  text ".PRJ_Number" at 3224,-656.17 h60
  text "BOARD #:" at 3769.5,-656.17 h60
  text "PCB VIEWED FROM BOTTOM SIDE" at 6246,-656.17 h60
  text "IGNORE ->" at 2547.85,-858.49 h60
  text "TEXAS INSTRUMENTS" at 904.5,-1064.84 h60
  text ".Print_Time" at 2169,-1064.84 h60
  text ".Print_Date" at 2898,-1064.84 h60
  text "GENERATED    :" at 3767.5,-1064.84 h60
  text ".plot_File_Name" at 5440.5,-1064.84 h60
  text "PLOT NAME =" at 6246,-1064.84 h60
M9 Title Sheet:
  drawing of 57 lines, arcs and shapes, not listed
  text "1" at 739.84,8036.5 h70
  text "2" at 3235.5,8036.5 h70
  text "3" at 5724.84,8036.5 h70
  text "4" at 8231.51,8036.5 h70
  text "5" at 10730.5,8036.5 h70
  text "6" at 13235.5,8036.5 h70
  text "A" at -416.5,6893.5 h70
  text "A" at 14383.5,6893.5 h70
  text "B" at -416.5,4513.5 h70
  text "B" at 14383.5,4513.5 h70
  text "C" at -416.5,2138.5 h70
  text "C" at 14383.5,2138.5 h70
  text "PROJECT TITLE:" at 11343.5,277.5 h45
  text ".PRJ_Title" at 11393.5,144.17 h70
  text "DESIGNED FOR:" at 11343.5,-23.5 h45
  text ".PRJ_Customer" at 11393.5,-163.5 h70
  text "D" at -416.5,-231.5 h70
  text "D" at 14383.5,-231.5 h70
  text "FILE NAME:" at 11343.5,-323.5 h45
  text ".PCB_File_Name_No_Path" at 11393.5,-443.5 h70
  text "Texas Instruments (TI) and/or its licensors do not warrant the accuracy or completeness of this specification" at 6374,-605.34 h45
  text "ENGINEER:" at 11343.5,-613.5 h45
  text "LAYOUT BY:" at 12848.5,-613.5 h45
  text "or any information contained therein. TI and/or its licensors do not warrant that this design will meet" at 6329.01,-718 h45
  text ".PRJ_Engineer" at 11393.5,-768.49 h70
  text ".PCB_Layout" at 12899,-768.49 h70
  text "the specifications, will be suitable for your application or fit for any particular purpose, or will operate in" at 6329.01,-830.67 h45
  text ".Layer_Name" at 577,-858.49 h60
  text "ALTIUM DESIGNER VERSION:" at 12848.5,-923.5 h45
  text "an implementation. TI and/or its licensors do not warrant that the design is production worthy. You should" at 6329.01,-943.33 h45
  text "completely validate and test your design implementation to confirm the system functionality for your application." at 6374,-1056 h45
  text ".print_Scale" at 11393.5,-1056.83 h70
  text ".Application_BuildNumber" at 12899,-1056.83 h70
  text "1" at 739.84,-1263.5 h70
  text "2" at 3235.5,-1263.5 h70
  text "3" at 5724.84,-1263.5 h70
  text "4" at 8231.51,-1263.5 h70
  text "5" at 10730.5,-1263.5 h70
  text "6" at 13235.5,-1263.5 h70
M10 Fab Notes:
  drawing of 212 lines, arcs and shapes, not listed
  text "DESIGN INFORMATION" at 12381.02,6810 h60
  text "(REFER ALSO ARRAY/PANEL PROFILING INFORMATION)" at 12019.46,6648.29 h60
  text "BOARD SIZE" at 11333.46,6644 h60
  text "3450MIL" at 11795.78,6516.18 h60
  text "X" at 12301.46,6516.18 h60
  text "4950MIL" at 12532.78,6516.18 h60
  text "Number of Layers :" at 11736.46,6319 h60
  text "2" at 12831.27,6309 h60
  text "MIN. TRACK WIDTH:" at 11736.46,6180 h60
  text "8" at 12832.7,6180 h60
  text "MIL" at 12987.46,6180 h60
  text "MIN. CLEARANCE:" at 11736.46,6048 h60
  text "8" at 12832.7,6048 h60
  text "MIL" at 12987.46,6048 h60
  text "MIN. VIA PAD SIZE:" at 11736.46,5916 h60
  text "24" at 12802.71,5916 h60
  text "MIL" at 12987.46,5916 h60
  text "0.05mm (2MIL)" at 12431.46,5774.29 h60
  text "MINIMUM ANNULAR RING" at 11407.23,5770 h60
  text "EXTERNAL" at 13139.46,5770 h60
  text "PER" at 11607.23,5652 h60
  text "IPC-D-275 CLASS 2 LEVEL C" at 11827.23,5652 h60
  text "MIL, HOLES" at 13315.46,5539.71 h60
  text "+/-" at 12923,5539 h60
  text "+/-" at 13777,5539 h60
  text "REGISTRATION TOLERANCES:" at 11407.23,5534 h60
  text "METAL" at 12607,5534 h60
  text "5" at 13183.2,5534 h60
  text "3" at 14016.2,5534 h60
  text "MIL" at 14132.46,5534 h60
  text "MATERIAL:" at 11332.46,5324.54 h60
  text "FR-4 High Tg" at 12318.9,5184.21 h60
  text "FR-408" at 11753.46,5175.64 h60
  text "X" at 12165.46,5175.64 h60
  text "OTHER" at 13241.46,5175.64 h60
  text "62 MIL (1.6mm) +/-10%" at 12073.56,5012.92 h60
  text "THICKNESS:" at 11407.23,5008.64 h60
  text "X" at 11945.4,5008.64 h60
  text "OTHER" at 13358.46,5008.64 h60
  text "TOLERANCE:" at 11407.23,4850.64 h60
  text "X" at 12246.53,4850.64 h60
  text "ANSI IPC-6012 TYPE 3 CLASS 2" at 12433.48,4850.64 h60
  text "OTHER +/-" at 12433.46,4694.64 h60
  text "BOW & TWIST:" at 11407.23,4537.64 h60
  text "X" at 12246.53,4537.64 h60
  text "ANSI IPC-6012 TYPE 3 CLASS 2" at 12433.48,4537.64 h60
  text "OTHER +/-" at 12433.46,4379.13 h60
  text "COPPER THICKNESS (FINISHED):" at 11332.46,4243.64 h60
  text "1.4MIL (1oz)" at 12212.46,4090.92 h60
  text "2MIL (1.4oz)" at 12979.46,4090.92 h60
  text "2.8MIL (2oz)" at 13706.46,4090.92 h60
  text "OUTER:" at 11689.46,4086.64 h60
  text "X" at 12859,4086 h60
  text "1.4MIL (1oz)" at 12212.46,3933.92 h60
  text "2.8MIL (2oz)" at 12979.46,3933.92 h60
  text "N/A" at 13706,3934.29 h60
  text "INNER SIGNAL:" at 11400.38,3929.64 h60
  text "X" at 12085.42,3929.64 h60
  text "DRILLING:" at 11332.46,3790.64 h60
  text "REFERENCE:" at 11407.23,3673.64 h60
  text "X" at 12055.46,3673.64 h60
  text "AS SHOWN" at 12242.46,3673.64 h60
  text "X" at 12956.46,3673.64 h60
  text "NC_DRILL FILES" at 13093.46,3673.64 h60
  text "PTH MIN COPPER THICKNESS:" at 11407.23,3515.64 h60
  text "X" at 12757.46,3515.64 h60
  text "1MIL" at 12894.46,3515.64 h60
  text "OTHER" at 13391.46,3515.64 h60
  text "BOARD FINISH:" at 11332.46,3356.64 h60
  text "SILKSCREEN:" at 11487.68,3238.64 h60
  text "X" at 12436.46,3238.64 h60
  text "TOP" at 12562.46,3238.64 h60
  text "X" at 12946.46,3238.64 h60
  text "BOTTOM" at 13073.46,3238.64 h60
  text "SILKSCREEN COLOR:" at 11487.68,3071.64 h60
  text "X" at 12435.42,3071.64 h60
  text "WHITE" at 12562.46,3071.64 h60
  text "OTHER" at 13073.46,3071.64 h60
  text "SOLDER RESIST COLOR:" at 11487.68,2901.64 h60
  text "X" at 12055.42,2742.44 h60
  text "GREEN" at 12182.46,2742.44 h60
  text "BLUE" at 12773.46,2742.44 h60
  text "OTHER" at 13311.46,2742.44 h60
  text "IMMERSION GOLD (ENIG)" at 12393.46,2553.92 h60
  text "ENEPIG" at 13731,2550.64 h60
  text "SURFACE FINISH:" at 11332.46,2549.64 h60
  text "X" at 12206.51,2549.64 h60
  text "IMM. TIN/SILVER OR EQUIV" at 11662,2392.64 h60
  text "OTHER" at 13093.46,2392.64 h60
  text "ARRAY/PANEL:" at 11332.46,2213.64 h60
  text "CUT AND TRIM PER MECH LAYER 1" at 12393.46,2209.35 h60
  text "N.C. ROUTE" at 12393.46,2057.64 h60
  text "X" at 13072.46,2057.64 h60
  text "V. SCORE" at 13259.46,2057.64 h60
  text "CERTIFICATION:" at 11332.46,1920.64 h60
  text "MATERIALS AND WORKMANSHIP FOR ALL PCBS" at 12057.46,1920.64 h60
  text "TO MEET OR EXCEED THE REQUIREMENTS OF:" at 12057.46,1822.64 h60
  text "X" at 11683.96,1686.13 h60
  text "ANSI IPC-A-600F CLASS ->" at 11822.96,1686.13 h60
  text "X" at 13462.02,1686.13 h60
  text "2" at 13580.96,1686.14 h60
  text "1" at 13265.96,1684.64 h60
  text "3" at 13934.96,1684.64 h60
  text "X" at 11686.02,1526.64 h60
  text "UL 94V-0" at 11822.96,1526.64 h60
  text "X" at 12498.02,1526.64 h60
  text "RoHS" at 12634.96,1526.64 h60
  text "OTHER" at 13279.36,1526.64 h60
  text "PER ORDER" at 13676.42,1526.64 h60
  text "ADDITIONAL REQUIREMENTS:" at 11332.46,1385.64 h60
  text "MICROSECTION:" at 11407.23,1270.64 h60
  text "YES" at 12312.96,1270.64 h60
  text "REQUIRED" at 13174.46,1114.49 h60
  text "BARE BOARD ELEC. TEST:" at 11407.23,1111.64 h60
  text "NONE" at 12712.96,1111.64 h60
  text "X" at 13047.46,1111.64 h60
  text "PER ORDER" at 13766.46,1111.64 h60
  text "MANUFACTURER'S UL:" at 11407.23,954.64 h60
  text "RAIL" at 12572.96,950.35 h60
  text "METAL" at 13064.77,950.35 h60
  text "X" at 13440,950 h60
  text "SILK" at 13576.46,950.35 h60
  text ".Layer_Name" at 577,-858.49 h60
M11 Gerber Information:
  lines w8: -292,-930.17 6308,-930.17 ; -292,-726.83 6310,-726.83 ; -292,-523.5 -292,-1133.5 3713,-1133.5 6310,-1133.5 6310,-523.5 -291.5,-523.5 -291.5,-1133.5 1284,-1133.5 ; 2173,-1133.5 2173,-523.5 ; 3440,-726.83 3440,-523.5 ; 4280,-726.83 4280,-523.5 ; 4902,-1140 4902,-937.17
  text "ALL ARTWORK VIEWED FROM TOP SIDE" at -228.5,-655.67 h60
  text "BOARD #:" at 2248,-655.67 h60
  text ".PRJ_Number" at 2793.5,-655.67 h60
  text "REV:" at 3638,-655.67 h60
  text ".PCB_Rev" at 3929.5,-655.67 h60
  text "SVN REV:" at 4476,-655.67 h60
  text ".VersionControl_RevNumber" at 4982,-655.67 h60
  text "LAYER NAME =" at -228.5,-858.49 h60
  text "PLOT NAME =" at -228.5,-1064.34 h60
  text ".plot_File_Name" at 577,-1064.34 h60
  text "GENERATED    :" at 2250,-1064.34 h60
  text ".Print_Date" at 3119.5,-1064.34 h60
  text ".Print_Time" at 3848.5,-1064.34 h60
  text "TEXAS INSTRUMENTS" at 5113,-1064.34 h60
M12 Stackup:
  lines w6: 11360,7460 13910,7460 ; 11360,7564.4 13910,7564.4 ; 11300,6975 ccw(c11334,6975) 11334,6941 13936,6941 ccw(c13936,6975) 13970,6975 13970,7681 ccw(c13936,7681) 13936,7715 11334,7715 ccw(c11334,7681) 11300,7681 11300,6975
  text "The Stackup Legend below this is static." at 11605.5,7874.5 h60
  text "If you change the stackup, update the Legend." at 11615.5,7784.5 h60
  text "Layer Stack Up Detail for: Ref_Design.PcbDoc" at 11360,7597.1 h57
  text "Layer" at 11360,7525.4 h24
  text "Gerber" at 12255.81,7525.4 h24
  text "Copper" at 12819.33,7525.4 h24
  text "Dielectric" at 13422.04,7525.4 h24
  text "Name" at 11360,7477.4 h24
  text "Document" at 12255.81,7477.4 h24
  text "Thickness" at 12819.33,7477.4 h24
  text "Material" at 13422.04,7477.4 h24
  text "Top Solder Mask" at 11360,7384.44 h34
  text "(.GTS)" at 12255.81,7384.44 h34
  text "Solder Resist" at 13422.04,7384.44 h34
  text "Top Layer" at 11360,7287.69 h34
  text "(.GTL)" at 12255.81,7287.69 h34
  text "1.4mil" at 12819.33,7287.69 h34
  text "FR-4" at 13422.04,7239.31 h34
  text "Bottom Layer" at 11360,7190.94 h34
  text "(.GBL)" at 12255.81,7190.94 h34
  text "1.4mil" at 12819.33,7190.94 h34
  text "Bottom Solder Mask" at 11360,7094.19 h34
  text "(.GBS)" at 12255.81,7094.19 h34
  text "Solder Resist" at 13422.04,7094.19 h34
  text ".Layer_Name" at 577,-858.49 h60
M13 Component Bodies Top:
  text ".Layer_Name" at 577,-858.49 h60
M14 Component Bodies Bottom:
  text ".Layer_Name" at 577,-858.49 h60
M15 Courtyards Top:
  text ".Layer_Name" at 577,-858.49 h60
M16 Courtyards Bottom:
  text ".Layer_Name" at 577,-858.49 h60
Drill Drawing:
  text ".legend" at 2242.5,905.5 h60
  text "Drill Table" at 2267.5,720.5 h60
  text ".Layer_Name" at 577,-858.49 h60

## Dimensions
0,0 to 0,3000 on M2 Board Dimensions
0,3000 to 2000,3000 on M2 Board Dimensions
0,0 to 0,3000 on M2 Board Dimensions
0,0 to 2000,0 on M2 Board Dimensions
